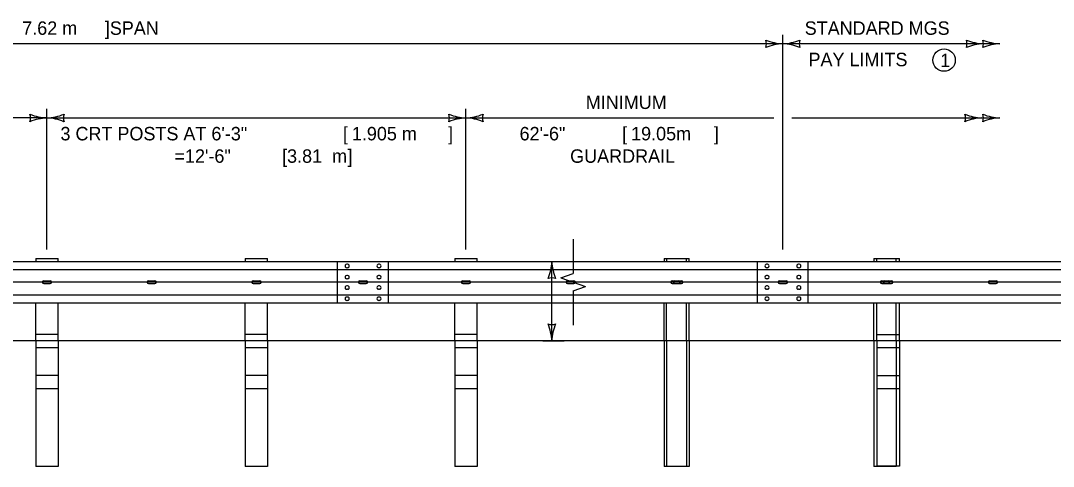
# Model space of a CAD drawing. Extents: x 49991.4 to 50044.5, y 49987.6 to 50011.4.
# Drawn here: x 50030.751 to 50035.357, y 50005.607 to 50007.595 of the extents above; entities that cross this region are included whole.
import ezdxf

# ---------------------------------------------------------------- set-up
doc = ezdxf.new("R2010")
doc.units = 0
for name, color, linetype in [('Level 1', 7, 'Continuous'), ('Level 2', 7, 'Continuous'), ('Level 3', 7, 'Continuous'), ('Level 4', 7, 'Continuous'), ('Level 5', 7, 'Continuous'), ('Level 6', 7, 'Continuous')]:
    doc.layers.add(name, color=color, linetype=linetype)

msp = doc.modelspace()

# ---------------------------------------------------------------- linework, layer by layer
at = {"layer": 'Level 1'}
for p, q in [((50023.8525, 50006.5203), (50035.1185, 50006.5203)), ((50030.818, 50006.5336), (50030.818, 50006.5203)), ((50030.818, 50006.5336), (50030.918, 50006.5336)), ((50030.918, 50006.5203), (50030.918, 50006.5336)), ((50031.7524, 50006.5336), (50031.7524, 50006.5203)), ((50031.7524, 50006.5336), (50031.8524, 50006.5336)), ((50031.8524, 50006.5203), (50031.8524, 50006.5336)), ((50032.1646, 50006.335), (50032.1646, 50006.5196)), ((50032.2088, 50006.508), (50032.2052, 50006.508)), ((50032.3511, 50006.508), (50032.3475, 50006.508)), ((50032.6869, 50006.5336), (50032.6869, 50006.5203)), ((50032.6869, 50006.5336), (50032.7868, 50006.5336)), ((50032.7868, 50006.5203), (50032.7868, 50006.5336)), ((50033.2149, 50006.5203), (50044.4809, 50006.5203)), ((50033.6213, 50006.5336), (50033.6213, 50006.5203)), ((50033.6213, 50006.5336), (50033.7213, 50006.5336)), ((50033.6321, 50006.5335), (50033.6321, 50006.5203)), ((50033.6321, 50006.5335), (50033.7321, 50006.5335)), ((50033.7213, 50006.5203), (50033.7213, 50006.5336)), ((50033.7321, 50006.5203), (50033.7321, 50006.5335)), ((50034.0371, 50006.335), (50034.0371, 50006.5196)), ((50034.0371, 50006.335), (50034.0371, 50006.5196)), ((50034.0813, 50006.508), (50034.0777, 50006.508)), ((50034.0813, 50006.508), (50034.0777, 50006.508)), ((50034.2235, 50006.508), (50034.2199, 50006.508)), ((50034.2235, 50006.508), (50034.2199, 50006.508)), ((50034.5558, 50006.5336), (50034.5558, 50006.5203)), ((50034.5558, 50006.5336), (50034.6557, 50006.5336)), ((50034.5701, 50006.5203), (50034.5701, 50006.5335)), ((50034.5701, 50006.5335), (50034.6701, 50006.5335)), ((50034.6557, 50006.5203), (50034.6557, 50006.5336)), ((50034.6701, 50006.5203), (50034.6701, 50006.5335)), ((50023.8525, 50006.4843), (50035.1185, 50006.4843)), ((50032.2088, 50006.4929), (50032.2052, 50006.4929)), ((50032.2088, 50006.4581), (50032.2052, 50006.4581)), ((50032.3511, 50006.4929), (50032.3475, 50006.4929)), ((50032.3511, 50006.4581), (50032.3475, 50006.4581)), ((50033.2149, 50006.4843), (50044.4809, 50006.4843)), ((50034.0813, 50006.4929), (50034.0777, 50006.4929)), ((50034.0813, 50006.4929), (50034.0777, 50006.4929)), ((50034.0813, 50006.4581), (50034.0777, 50006.4581)), ((50034.0813, 50006.4581), (50034.0777, 50006.4581)), ((50034.2235, 50006.4929), (50034.2199, 50006.4929)), ((50034.2235, 50006.4929), (50034.2199, 50006.4929)), ((50034.2235, 50006.4581), (50034.2199, 50006.4581)), ((50034.2235, 50006.4581), (50034.2199, 50006.4581)), ((50030.8534, 50006.4342), (50030.8826, 50006.4342)), ((50030.8534, 50006.4217), (50030.8826, 50006.4217)), ((50031.3206, 50006.4342), (50031.3498, 50006.4342)), ((50031.3206, 50006.4217), (50031.3498, 50006.4217)), ((50031.7878, 50006.4342), (50031.817, 50006.4342)), ((50031.7878, 50006.4217), (50031.817, 50006.4217)), ((50032.2088, 50006.443), (50032.2052, 50006.443)), ((50032.2088, 50006.4116), (50032.2052, 50006.4116)), ((50032.2633, 50006.4342), (50032.2924, 50006.4342)), ((50032.2633, 50006.4217), (50032.2924, 50006.4217)), ((50032.3511, 50006.443), (50032.3475, 50006.443)), ((50032.3511, 50006.4116), (50032.3475, 50006.4116)), ((50032.7223, 50006.4342), (50032.7514, 50006.4342)), ((50032.7223, 50006.4217), (50032.7514, 50006.4217)), ((50033.1895, 50006.4342), (50033.2187, 50006.4342)), ((50033.1895, 50006.4217), (50033.2187, 50006.4217)), ((50033.6567, 50006.4342), (50033.6859, 50006.4342)), ((50033.6567, 50006.4217), (50033.6859, 50006.4217)), ((50033.6685, 50006.4342), (50033.6977, 50006.4342)), ((50033.6685, 50006.4217), (50033.6977, 50006.4217)), ((50034.0813, 50006.443), (50034.0777, 50006.443)), ((50034.0813, 50006.443), (50034.0777, 50006.443)), ((50034.0813, 50006.4116), (50034.0777, 50006.4116)), ((50034.0813, 50006.4116), (50034.0777, 50006.4116)), ((50034.1358, 50006.4342), (50034.1649, 50006.4342)), ((50034.1358, 50006.4342), (50034.1649, 50006.4342)), ((50034.1358, 50006.4217), (50034.1649, 50006.4217)), ((50034.1358, 50006.4217), (50034.1649, 50006.4217)), ((50034.2235, 50006.443), (50034.2199, 50006.443)), ((50034.2235, 50006.443), (50034.2199, 50006.443)), ((50034.2235, 50006.4116), (50034.2199, 50006.4116)), ((50034.2235, 50006.4116), (50034.2199, 50006.4116)), ((50034.5912, 50006.4342), (50034.6203, 50006.4342)), ((50034.5912, 50006.4217), (50034.6203, 50006.4217)), ((50034.6055, 50006.4342), (50034.6347, 50006.4342)), ((50034.6055, 50006.4217), (50034.6347, 50006.4217)), ((50035.0728, 50006.4342), (50035.1019, 50006.4342)), ((50035.0728, 50006.4217), (50035.1019, 50006.4217)), ((50023.8525, 50006.3717), (50035.1185, 50006.3717)), ((50032.2088, 50006.3965), (50032.2052, 50006.3965)), ((50032.2088, 50006.3617), (50032.2052, 50006.3617)), ((50032.3511, 50006.3965), (50032.3475, 50006.3965)), ((50032.3511, 50006.3617), (50032.3475, 50006.3617)), ((50033.2149, 50006.3717), (50044.4809, 50006.3717)), ((50034.0813, 50006.3965), (50034.0777, 50006.3965)), ((50034.0813, 50006.3965), (50034.0777, 50006.3965)), ((50034.0813, 50006.3617), (50034.0777, 50006.3617)), ((50034.0813, 50006.3617), (50034.0777, 50006.3617)), ((50034.2235, 50006.3965), (50034.2199, 50006.3965)), ((50034.2235, 50006.3965), (50034.2199, 50006.3965)), ((50034.2235, 50006.3617), (50034.2199, 50006.3617)), ((50034.2235, 50006.3617), (50034.2199, 50006.3617)), ((50023.8525, 50006.3357), (50035.1185, 50006.3357)), ((50030.818, 50006.1659), (50030.818, 50006.3357)), ((50030.9179, 50006.1659), (50030.9179, 50006.3357)), ((50031.7524, 50006.1659), (50031.7524, 50006.3357)), ((50031.8523, 50006.1659), (50031.8523, 50006.3357)), ((50032.2088, 50006.3466), (50032.2052, 50006.3466)), ((50032.3511, 50006.3466), (50032.3475, 50006.3466)), ((50032.6869, 50006.1659), (50032.6869, 50006.3357)), ((50032.7868, 50006.1659), (50032.7868, 50006.3357)), ((50033.2149, 50006.3357), (50044.4809, 50006.3357)), ((50033.6213, 50006.1659), (50033.6213, 50006.3357)), ((50033.632, 50006.1659), (50033.632, 50006.3357)), ((50033.7212, 50006.1659), (50033.7212, 50006.3357)), ((50033.732, 50006.1659), (50033.732, 50006.3357)), ((50034.0813, 50006.3466), (50034.0777, 50006.3466)), ((50034.0813, 50006.3466), (50034.0777, 50006.3466)), ((50034.2235, 50006.3466), (50034.2199, 50006.3466)), ((50034.2235, 50006.3466), (50034.2199, 50006.3466)), ((50034.5558, 50006.1659), (50034.5558, 50006.3357)), ((50034.57, 50006.1659), (50034.57, 50006.3357)), ((50034.6557, 50006.1659), (50034.6557, 50006.3357)), ((50034.67, 50006.1659), (50034.67, 50006.3357)), ((50035.1185, 50006.1659), (50023.8525, 50006.1659)), ((50044.4809, 50006.1659), (50033.2149, 50006.1659))]:
    msp.add_line(p, q, dxfattribs=at)
for centre, start, end in [((50030.8534, 50006.428), 90, 180), ((50030.8534, 50006.428), 180, 270), ((50030.8826, 50006.428), 360, 90), ((50030.8826, 50006.428), 270, 0), ((50031.3206, 50006.428), 90, 180), ((50031.3206, 50006.428), 180, 270), ((50031.3498, 50006.428), 360, 90), ((50031.3498, 50006.428), 270, 0), ((50031.7878, 50006.428), 90, 180), ((50031.7878, 50006.428), 180, 270), ((50031.817, 50006.428), 360, 90), ((50031.817, 50006.428), 270, 0), ((50032.2633, 50006.428), 90, 180), ((50032.2633, 50006.428), 180, 270), ((50032.2924, 50006.428), 360, 90), ((50032.2924, 50006.428), 270, 0), ((50032.7223, 50006.428), 90, 180), ((50032.7223, 50006.428), 180, 270), ((50032.7514, 50006.428), 360, 90), ((50032.7514, 50006.428), 270, 0), ((50033.1895, 50006.428), 90, 180), ((50033.1895, 50006.428), 180, 270), ((50033.2187, 50006.428), 360, 90), ((50033.2187, 50006.428), 270, 0), ((50033.6567, 50006.428), 90, 180), ((50033.6567, 50006.428), 180, 270), ((50033.6685, 50006.428), 90, 180), ((50033.6685, 50006.428), 180, 270), ((50033.6859, 50006.428), 360, 90), ((50033.6859, 50006.428), 270, 0), ((50033.6977, 50006.428), 360, 90), ((50033.6977, 50006.428), 270, 0), ((50034.1358, 50006.428), 90, 180), ((50034.1358, 50006.428), 90, 180), ((50034.1358, 50006.428), 180, 270), ((50034.1358, 50006.428), 180, 270), ((50034.1649, 50006.428), 360, 90), ((50034.1649, 50006.428), 360, 90), ((50034.1649, 50006.428), 270, 0), ((50034.1649, 50006.428), 270, 0), ((50034.5912, 50006.428), 90, 180), ((50034.5912, 50006.428), 180, 270), ((50034.6055, 50006.428), 90, 180), ((50034.6055, 50006.428), 180, 270), ((50034.6203, 50006.428), 360, 90), ((50034.6203, 50006.428), 270, 0), ((50034.6347, 50006.428), 360, 90), ((50034.6347, 50006.428), 270, 0), ((50035.0728, 50006.428), 90, 180), ((50035.0728, 50006.428), 180, 270), ((50035.1019, 50006.428), 360, 90), ((50035.1019, 50006.428), 270, 0)]:
    msp.add_arc(centre, 0.00625, start, end, dxfattribs=at)
for centre, start_param, end_param in [((50032.2052, 50006.5004), 1.570796, 4.712389), ((50032.2088, 50006.5004), 4.712389, 7.853982), ((50032.3475, 50006.5004), 1.570796, 4.712389), ((50032.3511, 50006.5004), 4.712389, 7.853982), ((50034.0777, 50006.5004), 1.570796, 4.712389), ((50034.0777, 50006.5004), 1.570796, 4.712389), ((50034.0813, 50006.5004), 4.712389, 7.853982), ((50034.0813, 50006.5004), 4.712389, 7.853982), ((50034.2199, 50006.5004), 1.570796, 4.712389), ((50034.2199, 50006.5004), 1.570796, 4.712389), ((50034.2235, 50006.5004), 4.712389, 7.853982), ((50034.2235, 50006.5004), 4.712389, 7.853982), ((50032.2052, 50006.4505), 1.570796, 4.712389), ((50032.2088, 50006.4505), 4.712389, 7.853982), ((50032.3475, 50006.4505), 1.570796, 4.712389), ((50032.3511, 50006.4505), 4.712389, 7.853982), ((50034.0777, 50006.4505), 1.570796, 4.712389), ((50034.0777, 50006.4505), 1.570796, 4.712389), ((50034.0813, 50006.4505), 4.712389, 7.853982), ((50034.0813, 50006.4505), 4.712389, 7.853982), ((50034.2199, 50006.4505), 1.570796, 4.712389), ((50034.2199, 50006.4505), 1.570796, 4.712389), ((50034.2235, 50006.4505), 4.712389, 7.853982), ((50034.2235, 50006.4505), 4.712389, 7.853982), ((50032.2052, 50006.404), 1.570796, 4.712389), ((50032.2088, 50006.404), 4.712389, 7.853982), ((50032.3475, 50006.404), 1.570796, 4.712389), ((50032.3511, 50006.404), 4.712389, 7.853982), ((50034.0777, 50006.404), 1.570796, 4.712389), ((50034.0777, 50006.404), 1.570796, 4.712389), ((50034.0813, 50006.404), 4.712389, 7.853982), ((50034.0813, 50006.404), 4.712389, 7.853982), ((50034.2199, 50006.404), 1.570796, 4.712389), ((50034.2199, 50006.404), 1.570796, 4.712389), ((50034.2235, 50006.404), 4.712389, 7.853982), ((50034.2235, 50006.404), 4.712389, 7.853982), ((50032.2052, 50006.3541), 1.570796, 4.712389), ((50032.2088, 50006.3541), 4.712389, 7.853982), ((50032.3475, 50006.3541), 1.570796, 4.712389), ((50032.3511, 50006.3541), 4.712389, 7.853982), ((50034.0777, 50006.3541), 1.570796, 4.712389), ((50034.0777, 50006.3541), 1.570796, 4.712389), ((50034.0813, 50006.3541), 4.712389, 7.853982), ((50034.0813, 50006.3541), 4.712389, 7.853982), ((50034.2199, 50006.3541), 1.570796, 4.712389), ((50034.2199, 50006.3541), 1.570796, 4.712389), ((50034.2235, 50006.3541), 4.712389, 7.853982), ((50034.2235, 50006.3541), 4.712389, 7.853982)]:
    msp.add_ellipse(centre, major_axis=(0.00756, 0), ratio=0.998676, start_param=start_param, end_param=end_param, dxfattribs=at)
at = {"layer": 'Level 2'}
msp.add_circle((50034.8694, 50007.4187), 0.05, dxfattribs=at)
at = {"layer": 'Level 3'}
for p, q in [((50034.1503, 50006.5734), (50034.1503, 50007.5315)), ((50035.1185, 50007.4915), (50023.8525, 50007.4915)), ((50030.868, 50006.5736), (50030.868, 50007.2007)), ((50032.7369, 50006.5736), (50032.7369, 50007.2007)), ((50030.868, 50007.1607), (50027.1302, 50007.1607)), ((50030.868, 50007.1607), (50032.7369, 50007.1607)), ((50032.7369, 50007.1607), (50034.1103, 50007.1607)), ((50034.1903, 50007.1607), (50035.1185, 50007.1607)), ((50033.08, 50006.5203), (50033.1749, 50006.5203)), ((50033.12, 50006.1659), (50033.12, 50006.5203)), ((50033.08, 50006.1659), (50033.1749, 50006.1659))]:
    msp.add_line(p, q, dxfattribs=at)
for centre, radius, start, end in [((50034.1595, 50007.7137), 0.2223, 247.456, 267.6395), ((50034.0221, 50007.4915), 0.0548, 342.1388, 17.8612), ((50034.1618, 50007.2588), 0.233, 92.8273, 112.0772), ((50034.1388, 50007.7242), 0.233, 272.8273, 292.0772), ((50034.1412, 50007.2694), 0.2223, 67.456, 87.6395), ((50034.2786, 50007.4915), 0.0548, 162.1388, 197.8612), ((50035.0542, 50007.7137), 0.2223, 247.456, 267.6395), ((50034.9168, 50007.4915), 0.0548, 342.1388, 17.8612), ((50035.0565, 50007.2588), 0.233, 92.8273, 112.0772), ((50035.1277, 50007.7137), 0.2223, 247.456, 267.6395), ((50034.9903, 50007.4915), 0.0548, 342.1388, 17.8612), ((50035.13, 50007.2588), 0.233, 92.8273, 112.0772), ((50030.8771, 50007.3829), 0.2223, 247.456, 267.6395), ((50030.7398, 50007.1607), 0.0548, 342.1388, 17.8612), ((50030.8795, 50006.928), 0.233, 92.8273, 112.0772), ((50030.8565, 50007.3934), 0.233, 272.8273, 292.0772), ((50030.8588, 50006.9386), 0.2223, 67.456, 87.6395), ((50030.9962, 50007.1607), 0.0548, 162.1388, 197.8612), ((50032.746, 50007.3829), 0.2223, 247.456, 267.6395), ((50032.6086, 50007.1607), 0.0548, 342.1388, 17.8612), ((50032.7483, 50006.928), 0.233, 92.8273, 112.0772), ((50032.7254, 50007.3934), 0.233, 272.8273, 292.0772), ((50032.7277, 50006.9386), 0.2223, 67.456, 87.6395), ((50032.8651, 50007.1607), 0.0548, 162.1388, 197.8612), ((50034.9104, 50007.1607), 0.0548, 342.1388, 17.8612), ((50035.0501, 50007.3934), 0.233, 247.9228, 267.1727), ((50035.0477, 50006.9386), 0.2223, 92.3605, 112.544), ((50034.9903, 50007.1607), 0.0548, 342.1388, 17.8612), ((50035.13, 50007.3934), 0.233, 247.9228, 267.1727), ((50035.1277, 50006.9386), 0.2223, 92.3605, 112.544), ((50032.8978, 50006.5294), 0.2223, 337.456, 357.6395), ((50033.3527, 50006.5318), 0.233, 182.8273, 202.0772), ((50033.12, 50006.3921), 0.0548, 72.1388, 107.8612), ((50033.12, 50006.2941), 0.0548, 252.1388, 287.8612), ((50032.8872, 50006.1544), 0.233, 2.8273, 22.0772), ((50033.3421, 50006.1568), 0.2223, 157.456, 177.6395)]:
    msp.add_arc(centre, radius, start, end, dxfattribs=at)
at = {"layer": 'Level 4'}
for p, q in [((50032.3911, 50006.335), (50032.3911, 50006.5196)), ((50034.2636, 50006.335), (50034.2636, 50006.5196)), ((50034.2636, 50006.335), (50034.2636, 50006.5196)), ((50030.818, 50006.1957), (50030.9179, 50006.1957)), ((50031.7524, 50006.1957), (50031.8523, 50006.1957)), ((50032.6869, 50006.1957), (50032.7868, 50006.1957)), ((50034.5701, 50006.1945), (50034.67, 50006.1945)), ((50030.818, 50006.1659), (50030.818, 50005.6067)), ((50030.818, 50006.1374), (50030.9179, 50006.1374)), ((50030.9179, 50006.1659), (50030.9179, 50005.6067)), ((50031.7524, 50006.1659), (50031.7524, 50005.6067)), ((50031.7524, 50006.1374), (50031.8523, 50006.1374)), ((50031.8523, 50006.1659), (50031.8523, 50005.6067)), ((50032.6869, 50006.1659), (50032.6869, 50005.6067)), ((50032.6869, 50006.1374), (50032.7868, 50006.1374)), ((50032.7868, 50006.1659), (50032.7868, 50005.6067)), ((50033.6213, 50006.1659), (50033.6213, 50005.6067)), ((50033.632, 50006.1659), (50033.632, 50005.6067)), ((50033.7212, 50006.1659), (50033.7212, 50005.6067)), ((50033.732, 50006.1659), (50033.732, 50005.6067)), ((50034.5558, 50006.1659), (50034.5558, 50005.6067)), ((50034.57, 50006.1659), (50034.57, 50005.6078)), ((50034.5701, 50006.1362), (50034.67, 50006.1362)), ((50034.6557, 50006.1659), (50034.6557, 50005.6067)), ((50034.67, 50006.1659), (50034.67, 50005.6078)), ((50030.818, 50006.0127), (50030.9179, 50006.0127)), ((50031.7524, 50006.0127), (50031.8523, 50006.0127)), ((50032.6869, 50006.0127), (50032.7868, 50006.0127)), ((50034.5701, 50006.0116), (50034.67, 50006.0116)), ((50030.818, 50005.9544), (50030.9179, 50005.9544)), ((50031.7524, 50005.9544), (50031.8523, 50005.9544)), ((50032.6869, 50005.9544), (50032.7868, 50005.9544)), ((50034.5701, 50005.9533), (50034.67, 50005.9533)), ((50030.9179, 50005.6067), (50030.818, 50005.6067)), ((50031.8523, 50005.6067), (50031.7524, 50005.6067)), ((50032.7868, 50005.6067), (50032.6869, 50005.6067)), ((50033.7212, 50005.6067), (50033.6213, 50005.6067)), ((50033.732, 50005.6067), (50033.632, 50005.6067)), ((50034.6557, 50005.6067), (50034.5558, 50005.6067)), ((50034.67, 50005.6078), (50034.57, 50005.6078))]:
    msp.add_line(p, q, dxfattribs=at)
at = {"layer": 'Level 5'}
for p, q in [((50035.1185, 50006.428), (50023.8525, 50006.428)), ((50044.4809, 50006.428), (50033.2149, 50006.428))]:
    msp.add_line(p, q, dxfattribs=at)
at = {"layer": 'Level 6'}
for p, q in [((50033.2149, 50006.6203), (50033.2149, 50006.4669)), ((50033.16, 50006.4475), (50033.2149, 50006.4669)), ((50033.16, 50006.4475), (50033.2149, 50006.428)), ((50033.2149, 50006.428), (50033.2697, 50006.4086)), ((50033.2149, 50006.3891), (50033.2697, 50006.4086)), ((50033.2149, 50006.3891), (50033.2149, 50006.2357))]:
    msp.add_line(p, q, dxfattribs=at)

# ---------------------------------------------------------------- texts
at = {"layer": 'Level 2'}
for s, p in [('7.62 m', (50030.7577, 50007.5315)), (']', (50031.1266, 50007.5315)), (' SPAN', (50031.1261, 50007.5315)), ('STANDARD MGS', (50034.2478, 50007.5315)), ('PAY LIMITS', (50034.2647, 50007.3915)), ('1', (50034.8519, 50007.3873)), ('MINIMUM', (50033.2714, 50007.2007)), ('3 CRT POSTS AT 6\'-3" ', (50030.9283, 50007.0607)), ('[', (50032.1883, 50007.0607)), ('1.905 m', (50032.228, 50007.0607)), (']', (50032.657, 50007.0607)), (' 62\'-6" ', (50032.9537, 50007.0607)), ('[', (50033.4337, 50007.0607)), ('19.05m', (50033.4734, 50007.0607)), (']', (50033.8423, 50007.0607)), ('=12\'-6" ', (50031.4367, 50006.9607)), ('[3.81', (50031.9167, 50006.9607)), ('m', (50032.1397, 50006.9607)), (']', (50032.2086, 50006.9607)), ('GUARDRAIL', (50033.2016, 50006.9607))]:
    msp.add_text(s, height=0.06, dxfattribs=at).set_placement(p)

doc.saveas('drawing.dxf')
